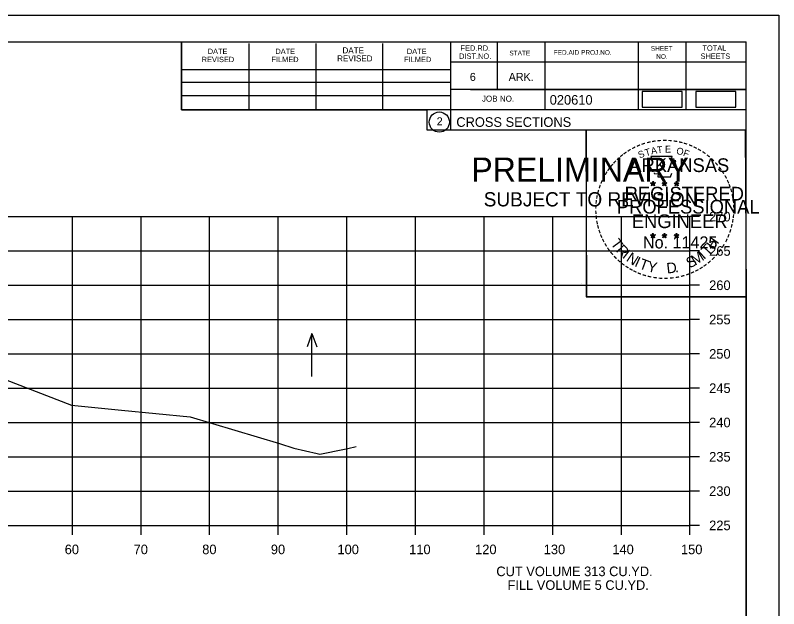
# Model space of a CAD drawing. Extents: x 1103485 to 1107180, y 2010593 to 2011873.
# Drawn here: x 1107068.9 to 1107180.1, y 2011573 to 2011659.5 of the extents above; entities that cross this region are included whole.
import ezdxf

# ---------------------------------------------------------------- set-up
doc = ezdxf.new("R2010")
doc.units = 0
for name, color, linetype in [('R_Axis', 7, 'Continuous'), ('R_Axis Annot', 7, 'Continuous'), ('R_Border', 7, 'Continuous'), ('R_Border PE', 7, 'Continuous'), ('R_Border Prem', 7, 'Continuous'), ('R_Exist Surface', 7, 'Continuous'), ('R_Grid', 7, 'Continuous'), ('R_No Plot', 7, 'Continuous'), ('R_Water', 7, 'Continuous'), ('R_Water Annot', 7, 'Continuous')]:
    doc.layers.add(name, color=color, linetype=linetype)

msp = doc.modelspace()

# ---------------------------------------------------------------- linework, layer by layer
at = {"layer": 'R_Axis'}
for p, q in [((1107167.18, 2011585.17), (1107167.18, 2011630.17)), ((1107168.58, 2011630.17), (1107167.18, 2011630.17)), ((1107168.58, 2011625.17), (1107167.18, 2011625.17)), ((1107168.58, 2011620.17), (1107167.18, 2011620.17)), ((1107168.58, 2011615.17), (1107167.18, 2011615.17)), ((1107168.58, 2011610.17), (1107167.18, 2011610.17)), ((1107168.58, 2011605.17), (1107167.18, 2011605.17)), ((1107168.58, 2011600.17), (1107167.18, 2011600.17)), ((1107168.58, 2011595.17), (1107167.18, 2011595.17)), ((1107168.58, 2011590.17), (1107167.18, 2011590.17)), ((1106867.18, 2011585.17), (1107167.18, 2011585.17)), ((1107077.18, 2011583.77), (1107077.18, 2011585.17)), ((1107087.18, 2011583.77), (1107087.18, 2011585.17)), ((1107097.18, 2011583.77), (1107097.18, 2011585.17)), ((1107107.18, 2011583.77), (1107107.18, 2011585.17)), ((1107117.18, 2011583.77), (1107117.18, 2011585.17)), ((1107127.18, 2011583.77), (1107127.18, 2011585.17)), ((1107137.18, 2011583.77), (1107137.18, 2011585.17)), ((1107147.18, 2011583.77), (1107147.18, 2011585.17)), ((1107157.18, 2011583.77), (1107157.18, 2011585.17)), ((1107167.18, 2011583.77), (1107167.18, 2011585.17)), ((1107168.58, 2011585.17), (1107167.18, 2011585.17))]:
    msp.add_line(p, q, dxfattribs=at)
at = {"layer": 'R_Border'}
for p, q in [((1106859.18, 2011655.63), (1107175.36, 2011655.63)), ((1107093.1, 2011645.75), (1107093.1, 2011655.63)), ((1107102.96, 2011645.75), (1107102.96, 2011655.43)), ((1107112.72, 2011645.75), (1107112.72, 2011655.43)), ((1107122.4, 2011645.75), (1107122.4, 2011655.43)), ((1107132.26, 2011655.63), (1107132.26, 2011642.83)), ((1107139.1, 2011655.63), (1107139.1, 2011648.69)), ((1107146.04, 2011655.63), (1107146.04, 2011645.75)), ((1107159.62, 2011655.63), (1107159.62, 2011645.75)), ((1107166.56, 2011655.63), (1107166.56, 2011645.75)), ((1107175.36, 2011450.17), (1107175.36, 2011655.63)), ((1107175.36, 2011652.69), (1107132.26, 2011652.69)), ((1107175.36, 2011652.71), (1107175.36, 2011652.71)), ((1107093.1, 2011651.61), (1107132.26, 2011651.61)), ((1107093.1, 2011649.75), (1107132.26, 2011649.75)), ((1107175.36, 2011648.69), (1107132.26, 2011648.69)), ((1107135.22, 2011648.69), (1107175.36, 2011648.69)), ((1107093.1, 2011645.75), (1107093.1, 2011647.81)), ((1107093.1, 2011647.81), (1107132.26, 2011647.81)), ((1107175.36, 2011645.75), (1107093.1, 2011645.75)), ((1107132.26, 2011642.83), (1107175.36, 2011642.83))]:
    msp.add_line(p, q, dxfattribs=at)
msp.add_circle((1107130.65, 2011643.96), 1.47, dxfattribs=at)
at = {"layer": 'R_Border PE'}
for p, q in [((1107161.45, 2011635.08), (1107161.8, 2011634.97)), ((1107161.45, 2011635.08), (1107161.7, 2011635.04)), ((1107161.45, 2011635.08), (1107161.69, 2011634.96)), ((1107161.8, 2011635.34), (1107161.76, 2011635.09)), ((1107161.8, 2011634.97), (1107161.8, 2011635.34)), ((1107161.8, 2011635.34), (1107161.85, 2011635.09)), ((1107162.14, 2011635.08), (1107161.8, 2011634.97)), ((1107162.14, 2011635.08), (1107161.86, 2011635.03)), ((1107162.14, 2011635.08), (1107161.94, 2011634.98)), ((1107163.12, 2011635.08), (1107163.47, 2011634.97)), ((1107163.12, 2011635.08), (1107163.37, 2011635.04)), ((1107163.12, 2011635.08), (1107163.36, 2011634.96)), ((1107163.47, 2011635.34), (1107163.43, 2011635.09)), ((1107163.47, 2011634.97), (1107163.47, 2011635.34)), ((1107163.47, 2011635.34), (1107163.52, 2011635.09)), ((1107163.81, 2011635.08), (1107163.47, 2011634.97)), ((1107163.81, 2011635.08), (1107163.53, 2011635.03)), ((1107163.81, 2011635.08), (1107163.61, 2011634.98)), ((1107164.88, 2011635.07), (1107165.23, 2011634.96)), ((1107164.88, 2011635.07), (1107165.14, 2011635.03)), ((1107164.88, 2011635.07), (1107165.12, 2011634.95)), ((1107165.23, 2011635.33), (1107165.19, 2011635.07)), ((1107165.23, 2011634.96), (1107165.23, 2011635.33)), ((1107165.23, 2011635.33), (1107165.28, 2011635.08)), ((1107165.58, 2011635.07), (1107165.23, 2011634.96)), ((1107165.58, 2011635.07), (1107165.29, 2011635.02)), ((1107165.58, 2011635.07), (1107165.37, 2011634.97)), ((1107161.58, 2011634.68), (1107161.8, 2011634.97)), ((1107161.58, 2011634.68), (1107161.71, 2011634.92)), ((1107161.58, 2011634.68), (1107161.8, 2011634.89)), ((1107162.01, 2011634.68), (1107161.8, 2011634.97)), ((1107162.01, 2011634.68), (1107161.8, 2011634.89)), ((1107162.01, 2011634.68), (1107161.87, 2011634.97)), ((1107163.25, 2011634.68), (1107163.47, 2011634.97)), ((1107163.25, 2011634.68), (1107163.38, 2011634.92)), ((1107163.25, 2011634.68), (1107163.47, 2011634.89)), ((1107163.68, 2011634.68), (1107163.47, 2011634.97)), ((1107163.68, 2011634.68), (1107163.47, 2011634.89)), ((1107163.68, 2011634.68), (1107163.54, 2011634.97)), ((1107165.02, 2011634.66), (1107165.23, 2011634.96)), ((1107165.02, 2011634.66), (1107165.14, 2011634.91)), ((1107165.02, 2011634.66), (1107165.23, 2011634.88)), ((1107165.44, 2011634.66), (1107165.23, 2011634.96)), ((1107165.44, 2011634.66), (1107165.23, 2011634.88)), ((1107165.44, 2011634.66), (1107165.31, 2011634.95)), ((1107161.44, 2011627.51), (1107161.79, 2011627.4)), ((1107161.44, 2011627.51), (1107161.7, 2011627.47)), ((1107161.44, 2011627.51), (1107161.68, 2011627.39)), ((1107161.58, 2011627.1), (1107161.79, 2011627.4)), ((1107161.58, 2011627.1), (1107161.7, 2011627.35)), ((1107161.58, 2011627.1), (1107161.79, 2011627.32)), ((1107161.79, 2011627.76), (1107161.75, 2011627.51)), ((1107161.79, 2011627.4), (1107161.79, 2011627.76)), ((1107161.79, 2011627.76), (1107161.84, 2011627.51)), ((1107162.14, 2011627.51), (1107161.79, 2011627.4)), ((1107162.01, 2011627.1), (1107161.79, 2011627.4)), ((1107162.01, 2011627.1), (1107161.79, 2011627.32)), ((1107162.14, 2011627.51), (1107161.85, 2011627.46)), ((1107162.01, 2011627.1), (1107161.87, 2011627.39)), ((1107162.14, 2011627.51), (1107161.94, 2011627.41)), ((1107163.11, 2011627.51), (1107163.46, 2011627.4)), ((1107163.11, 2011627.51), (1107163.37, 2011627.47)), ((1107163.11, 2011627.51), (1107163.35, 2011627.39)), ((1107163.25, 2011627.1), (1107163.46, 2011627.4)), ((1107163.25, 2011627.1), (1107163.37, 2011627.35)), ((1107163.25, 2011627.1), (1107163.46, 2011627.32)), ((1107163.46, 2011627.76), (1107163.42, 2011627.51)), ((1107163.46, 2011627.4), (1107163.46, 2011627.76)), ((1107163.46, 2011627.76), (1107163.51, 2011627.51)), ((1107163.81, 2011627.51), (1107163.46, 2011627.4)), ((1107163.68, 2011627.1), (1107163.46, 2011627.4)), ((1107163.68, 2011627.1), (1107163.46, 2011627.32)), ((1107163.81, 2011627.51), (1107163.52, 2011627.46)), ((1107163.68, 2011627.1), (1107163.54, 2011627.39)), ((1107163.81, 2011627.51), (1107163.61, 2011627.41)), ((1107164.88, 2011627.5), (1107165.23, 2011627.39)), ((1107164.88, 2011627.5), (1107165.13, 2011627.46)), ((1107164.88, 2011627.5), (1107165.12, 2011627.38)), ((1107165.01, 2011627.09), (1107165.23, 2011627.39)), ((1107165.01, 2011627.09), (1107165.14, 2011627.34)), ((1107165.01, 2011627.09), (1107165.23, 2011627.31)), ((1107165.23, 2011627.75), (1107165.19, 2011627.5)), ((1107165.23, 2011627.39), (1107165.23, 2011627.75)), ((1107165.23, 2011627.75), (1107165.28, 2011627.5)), ((1107165.58, 2011627.5), (1107165.23, 2011627.39)), ((1107165.44, 2011627.09), (1107165.23, 2011627.39)), ((1107165.44, 2011627.09), (1107165.23, 2011627.31)), ((1107165.58, 2011627.5), (1107165.29, 2011627.45)), ((1107165.44, 2011627.09), (1107165.31, 2011627.38)), ((1107165.58, 2011627.5), (1107165.37, 2011627.4))]:
    msp.add_line(p, q, dxfattribs=at)
for points in [[(1107161.49, 2011638.96), (1107161.76, 2011638.13)], [(1107165, 2011638.04), (1107165.14, 2011638.32), (1107164.46, 2011638.3), (1107164.61, 2011638.96), (1107161.49, 2011638.96)], [(1107161.98, 2011636.54), (1107161.98, 2011636.45), (1107162.54, 2011636.43), (1107162.49, 2011635.96), (1107164.36, 2011635.96), (1107164.56, 2011636.5)], [(1107161.8, 2011635.34), (1107162.01, 2011634.68), (1107161.45, 2011635.08), (1107162.14, 2011635.08), (1107161.58, 2011634.68), (1107161.8, 2011635.34)], [(1107163.47, 2011635.34), (1107163.68, 2011634.68), (1107163.12, 2011635.08), (1107163.81, 2011635.08), (1107163.25, 2011634.68), (1107163.47, 2011635.34)], [(1107165.23, 2011635.33), (1107165.44, 2011634.66), (1107164.88, 2011635.07), (1107165.58, 2011635.07), (1107165.02, 2011634.66), (1107165.23, 2011635.33)], [(1107161.79, 2011627.76), (1107162.01, 2011627.1), (1107161.44, 2011627.51), (1107162.14, 2011627.51), (1107161.58, 2011627.1), (1107161.79, 2011627.76)], [(1107163.46, 2011627.76), (1107163.68, 2011627.1), (1107163.11, 2011627.51), (1107163.81, 2011627.51), (1107163.25, 2011627.1), (1107163.46, 2011627.76)], [(1107165.23, 2011627.75), (1107165.44, 2011627.09), (1107164.88, 2011627.5), (1107165.58, 2011627.5), (1107165.01, 2011627.09), (1107165.23, 2011627.75)]]:
    msp.add_lwpolyline(points, dxfattribs=at)
for centre, radius in [((1107161.8, 2011634.97), 0.172), ((1107161.8, 2011634.97), 0.145), ((1107161.8, 2011634.97), 0.116), ((1107161.8, 2011634.97), 0.0991), ((1107161.8, 2011634.97), 0.0747), ((1107163.47, 2011634.97), 0.172), ((1107163.47, 2011634.97), 0.145), ((1107163.47, 2011634.97), 0.116), ((1107163.47, 2011634.97), 0.0991), ((1107163.47, 2011634.97), 0.0747), ((1107165.23, 2011634.96), 0.172), ((1107165.23, 2011634.96), 0.145), ((1107165.23, 2011634.96), 0.116), ((1107165.23, 2011634.96), 0.0991), ((1107161.8, 2011634.97), 0.0495), ((1107161.8, 2011634.97), 0.0296), ((1107163.47, 2011634.97), 0.0495), ((1107163.47, 2011634.97), 0.0296), ((1107165.23, 2011634.96), 0.0747), ((1107165.23, 2011634.96), 0.0495), ((1107165.23, 2011634.96), 0.0296), ((1107161.79, 2011627.4), 0.172), ((1107161.79, 2011627.4), 0.145), ((1107161.79, 2011627.4), 0.116), ((1107161.79, 2011627.4), 0.0991), ((1107161.79, 2011627.4), 0.0747), ((1107161.79, 2011627.4), 0.0495), ((1107161.79, 2011627.4), 0.0296), ((1107163.46, 2011627.4), 0.172), ((1107163.46, 2011627.4), 0.145), ((1107163.46, 2011627.4), 0.116), ((1107163.46, 2011627.4), 0.0991), ((1107163.46, 2011627.4), 0.0747), ((1107163.46, 2011627.4), 0.0495), ((1107163.46, 2011627.4), 0.0296), ((1107165.23, 2011627.39), 0.172), ((1107165.23, 2011627.39), 0.145), ((1107165.23, 2011627.39), 0.116), ((1107165.23, 2011627.39), 0.0991), ((1107165.23, 2011627.39), 0.0747), ((1107165.23, 2011627.39), 0.0495), ((1107165.23, 2011627.39), 0.0296)]:
    msp.add_circle(centre, radius, dxfattribs=at)
at = {"layer": 'R_Exist Surface'}
msp.add_lwpolyline([(1107058.31, 2011609.94), (1107077.03, 2011602.69), (1107084.35, 2011601.97), (1107094.32, 2011601), (1107107.35, 2011597.1), (1107109.47, 2011596.44), (1107112.84, 2011595.63), (1107113.26, 2011595.53), (1107116.85, 2011596.28), (1107117.3, 2011596.38), (1107118.54, 2011596.65)], dxfattribs=at)
at = {"layer": 'R_Grid'}
for p, q in [((1106867.18, 2011630.17), (1107167.18, 2011630.17)), ((1107077.18, 2011585.17), (1107077.18, 2011630.17)), ((1107087.18, 2011585.17), (1107087.18, 2011630.17)), ((1107097.18, 2011585.17), (1107097.18, 2011630.17)), ((1107107.18, 2011585.17), (1107107.18, 2011630.17)), ((1107117.18, 2011585.17), (1107117.18, 2011630.17)), ((1107127.18, 2011585.17), (1107127.18, 2011630.17)), ((1107137.18, 2011585.17), (1107137.18, 2011630.17)), ((1107147.18, 2011585.17), (1107147.18, 2011630.17)), ((1107157.18, 2011585.17), (1107157.18, 2011630.17)), ((1107167.18, 2011585.17), (1107167.18, 2011630.17)), ((1106867.18, 2011625.17), (1107167.18, 2011625.17)), ((1106867.18, 2011620.17), (1107167.18, 2011620.17)), ((1106867.18, 2011615.17), (1107167.18, 2011615.17)), ((1106867.18, 2011610.17), (1107167.18, 2011610.17)), ((1106867.18, 2011605.17), (1107167.18, 2011605.17)), ((1106867.18, 2011600.17), (1107167.18, 2011600.17)), ((1106867.18, 2011595.17), (1107167.18, 2011595.17)), ((1106867.18, 2011590.17), (1107167.18, 2011590.17)), ((1106867.18, 2011585.17), (1107167.18, 2011585.17))]:
    msp.add_line(p, q, dxfattribs=at)
at = {"layer": 'R_No Plot'}
for p, q in [((1106846.78, 2011659.52), (1107180.12, 2011659.52)), ((1107151.4, 2011620.37), (1107151.4, 2011620.37))]:
    msp.add_line(p, q, dxfattribs=at)
for points in [[(1106846.78, 2011659.52), (1107180.12, 2011659.52), (1107180.12, 2011446.19), (1106846.78, 2011446.19)], [(1107093.1, 2011655.63), (1107093.1, 2011645.75), (1107128.84, 2011645.75), (1107128.84, 2011642.83), (1107152.04, 2011642.83), (1107152.04, 2011618.5), (1107175.36, 2011618.5), (1107175.36, 2011450.17), (1106859.18, 2011450.17), (1106859.18, 2011655.63)], [(1107152.04, 2011642.83), (1107175.24, 2011642.83), (1107175.36, 2011618.5), (1107152.16, 2011618.5)]]:
    msp.add_lwpolyline(points, close=True, dxfattribs=at)
at = {"layer": 'R_Water'}
for points in [[(1107160.2, 2011646.12), (1107166.03, 2011646.12), (1107166.03, 2011648.43), (1107160.2, 2011648.43)], [(1107168.04, 2011646.12), (1107173.87, 2011646.12), (1107173.87, 2011648.43), (1107168.04, 2011648.43)]]:
    msp.add_lwpolyline(points, close=True, dxfattribs=at)
at = {"layer": 'R_Water Annot'}
for p, q in [((1107112.08, 2011613.14), (1107111.38, 2011611.22)), ((1107112.08, 2011606.86), (1107112.08, 2011613.14)), ((1107112.08, 2011613.14), (1107112.78, 2011611.22))]:
    msp.add_line(p, q, dxfattribs=at)

# ---------------------------------------------------------------- texts
at = {"layer": 'R_Axis Annot'}
for s, p in [('270', (1107169.98, 2011629.47)), ('265', (1107169.98, 2011624.47)), ('260', (1107169.98, 2011619.47)), ('255', (1107169.98, 2011614.47)), ('250', (1107169.98, 2011609.47)), ('245', (1107169.98, 2011604.47)), ('240', (1107169.98, 2011599.47)), ('235', (1107169.98, 2011594.47)), ('230', (1107169.98, 2011589.47)), ('225', (1107169.98, 2011584.47)), ('60', (1107076.06, 2011580.97)), ('70', (1107086.1, 2011580.97)), ('80', (1107096.1, 2011580.97)), ('90', (1107106.1, 2011580.97)), ('100', (1107115.81, 2011580.97)), ('110', (1107126.26, 2011580.97)), ('120', (1107135.87, 2011580.97)), ('130', (1107145.87, 2011580.97)), ('140', (1107155.87, 2011580.97)), ('150', (1107165.87, 2011580.97)), ('CUT VOLUME 313 CU.YD.', (1107138.96, 2011577.77)), ('FILL VOLUME 5 CU.YD.', (1107140.59, 2011575.77))]:
    msp.add_text(s, height=1.4, dxfattribs=at).set_placement(p)
at = {"layer": 'R_Border'}
for s, height, p in [('FED.RD.', 0.782, (1107133.74, 2011654.35)), ('TOTAL', 0.782, (1107169, 2011654.35)), ('DATE', 0.782, (1107096.9, 2011653.87)), ('DATE', 0.782, (1107106.76, 2011653.87)), ('DATE', 0.879, (1107116.54, 2011653.97)), ('DATE', 0.782, (1107125.92, 2011653.87)), ('DIST.NO.', 0.782, (1107133.54, 2011653.17)), ('STATE', 0.684, (1107140.86, 2011653.67)), ('FED.AID PROJ.NO.', 0.684, (1107147.32, 2011653.77)), ('SHEET', 0.684, (1107161.48, 2011654.35)), ('SHEETS', 0.782, (1107168.72, 2011653.17)), ('REVISED', 0.782, (1107096.02, 2011652.69)), ('FILMED', 0.782, (1107106.18, 2011652.69)), ('REVISED', 0.879, (1107115.76, 2011652.79)), ('FILMED', 0.782, (1107125.52, 2011652.69)), ('NO.', 0.684, (1107162.26, 2011653.17)), ('6', 1.17, (1107135.1, 2011649.95)), ('ARK.', 1.172, (1107140.76, 2011649.95)), ('JOB NO.', 0.879, (1107136.86, 2011646.93)), ('020610', 1.4, (1107146.74, 2011646.49)), ('2', 1.17, (1107130.27, 2011643.48)), ('CROSS SECTIONS', 1.4, (1107133.13, 2011643.26))]:
    msp.add_text(s, height=height, rotation=360, dxfattribs=at).set_placement(p)
at = {"layer": 'R_Border PE'}
for s, height, rotation, p in [('-', 1.6, 24.3072, (1107159.6, 2011639.82)), ('-', 1.6, 19.1761, (1107160.24, 2011640.09)), ('-', 1.6, 13.6301, (1107160.99, 2011640.33)), ('-', 1.6, 10.2193, (1107161.67, 2011640.49)), ('-', 1.6, 5.8968, (1107162.39, 2011640.6)), ('-', 1.6, 0.1862, (1107163.17, 2011640.67)), ('-', 1.6, 357.743, (1107163.89, 2011640.66)), ('-', 1.6, 352.1617, (1107164.63, 2011640.6)), ('-', 1.6, 347.2049, (1107165.35, 2011640.49)), ('-', 1.6, 342.3362, (1107165.99, 2011640.34)), ('-', 1.6, 337.8551, (1107166.72, 2011640.11)), ('-', 1.6, 36.2317, (1107157.8, 2011638.74)), ('-', 1.6, 34.0636, (1107158.37, 2011639.13)), ('-', 1.6, 28.7918, (1107158.97, 2011639.5)), ('S', 1, 21.594, (1107159.84, 2011638.64)), ('T', 1, 16.4036, (1107160.76, 2011638.97)), ('A', 1, 11.2132, (1107161.58, 2011639.22)), ('T', 1, 6.0228, (1107162.43, 2011639.39)), ('E', 1, 0.8323, (1107163.54, 2011639.5)), ('O', 1, 350.4515, (1107165.14, 2011639.29)), ('F', 1, 340.0707, (1107166.1, 2011639.06)), ('-', 1.6, 334.1211, (1107167.35, 2011639.84)), ('-', 1.6, 329.6409, (1107167.93, 2011639.56)), ('-', 1.6, 325.8627, (1107168.58, 2011639.2)), ('-', 1.6, 48.423, (1107156.44, 2011637.46)), ('-', 1.6, 42.9622, (1107156.89, 2011637.94)), ('-', 1.6, 38.9507, (1107157.32, 2011638.36)), ('ARKANSAS', 2, 360, (1107158.34, 2011636.67)), ('-', 1.6, 320.5297, (1107169.19, 2011638.77)), ('-', 1.6, 315.5786, (1107169.78, 2011638.28)), ('-', 1.6, 54.2325, (1107155.62, 2011636.41)), ('-', 1.6, 50.6142, (1107156.04, 2011636.98)), ('-', 1.6, 309.8797, (1107170.35, 2011637.73)), ('-', 1.6, 306.6522, (1107170.88, 2011637.13)), ('-', 1.6, 58.0706, (1107155.3, 2011635.88)), ('-', 1.4, 303.6753, (1107171.36, 2011636.56)), ('-', 1.6, 299.6684, (1107171.68, 2011635.96)), ('-', 1.6, 67.7743, (1107154.73, 2011634.66)), ('-', 1.6, 62.8713, (1107154.98, 2011635.27)), ('-', 1.6, 294.6628, (1107172.01, 2011635.34)), ('-', 1.6, 75.461, (1107154.31, 2011633.32)), ('-', 1.6, 72.3945, (1107154.51, 2011634.03)), ('REGISTERED', 2, 360, (1107157.66, 2011632.52)), ('DWB', 0.01, 360, (1107161.78, 2011634.97)), ('DWB', 0.01, 360, (1107163.45, 2011634.97)), ('DWB', 0.01, 360, (1107165.22, 2011634.96)), ('-', 1.6, 290.5728, (1107172.26, 2011634.77)), ('-', 1.6, 285.1233, (1107172.5, 2011634.19)), ('-', 1.6, 81.2013, (1107154.18, 2011632.6)), ('-', 1.6, 280.5493, (1107172.7, 2011633.45)), ('-', 1.6, 89.0622, (1107154.08, 2011631.21)), ('-', 1.6, 85.1863, (1107154.1, 2011631.91)), ('PROFESSIONAL', 2, 360, (1107156.52, 2011630.62)), ('-', 1.6, 276.5962, (1107172.86, 2011632.68)), ('-', 1.6, 274.3301, (1107172.92, 2011631.96)), ('-', 1.6, 94.1959, (1107154.11, 2011630.49)), ('-', 1.6, 269.9407, (1107172.95, 2011631.32)), ('-', 1.6, 98.9479, (1107154.18, 2011629.82)), ('-', 1.6, 101.7149, (1107154.32, 2011629.09)), ('ENGINEER', 2, 360, (1107158.7, 2011628.5)), ('-', 1.6, 260.9953, (1107172.86, 2011630)), ('-', 1.6, 263.5172, (1107172.94, 2011630.66)), ('-', 1.6, 105.4578, (1107154.48, 2011628.49)), ('-', 1.6, 255.7626, (1107172.75, 2011629.33)), ('-', 1.6, 109.0874, (1107154.7, 2011627.86)), ('-', 1.6, 114.0643, (1107154.95, 2011627.26)), ('No. 11425', 1.757, 360, (1107160.33, 2011625.54)), ('DWB', 0.01, 360, (1107161.78, 2011627.39)), ('DWB', 0.01, 360, (1107163.45, 2011627.4)), ('DWB', 0.01, 360, (1107165.22, 2011627.39)), ('-', 1.6, 247.8887, (1107172.35, 2011627.93)), ('-', 1.6, 252.8681, (1107172.57, 2011628.61)), ('-', 1.6, 115.7289, (1107155.25, 2011626.65)), ('-', 1.6, 120.4471, (1107155.61, 2011626.06)), ('T', 1.54, 306.0406, (1107155.55, 2011626.24)), ('T', 1.54, 46.6444, (1107169.78, 2011624.33)), ('H', 1.54, 54.6088, (1107170.67, 2011625.27)), ('-', 1.6, 239.0712, (1107171.69, 2011626.55)), ('-', 1.6, 244.6197, (1107172.09, 2011627.3)), ('-', 1.6, 125.8934, (1107156.01, 2011625.5)), ('-', 1.6, 130.7181, (1107156.48, 2011624.95)), ('R', 1.54, 314.005, (1107156.32, 2011625.19)), ('I', 1.54, 321.9694, (1107157.22, 2011624.26)), ('M', 1.54, 32.6563, (1107167.94, 2011623.01)), ('I', 1.54, 42.1136, (1107169.22, 2011623.85)), ('-', 1.6, 233.8452, (1107171.29, 2011625.9)), ('-', 1.6, 134.2238, (1107156.99, 2011624.4)), ('-', 1.6, 138.9338, (1107157.52, 2011623.94)), ('N', 1.54, 326.5002, (1107157.78, 2011623.79)), ('I', 1.54, 335.3603, (1107158.99, 2011623)), ('T', 1.54, 339.8912, (1107159.65, 2011622.67)), ('S', 1.54, 26.9312, (1107167.1, 2011622.6)), ('-', 1.6, 225.7653, (1107170.38, 2011624.77)), ('-', 1.6, 231.2538, (1107170.86, 2011625.33)), ('-', 1.6, 144.6463, (1107158.07, 2011623.53)), ('-', 1.6, 148.0898, (1107158.64, 2011623.16)), ('Y', 1.54, 347.8556, (1107160.87, 2011622.23)), ('D', 1.54, 6.3969, (1107163.85, 2011621.87)), ('-', 1.6, 212.2491, (1107168.78, 2011623.4)), ('-', 1.6, 215.7363, (1107169.31, 2011623.79)), ('-', 1.6, 221.0851, (1107169.86, 2011624.26)), ('-', 1.6, 151.5704, (1107159.21, 2011622.84)), ('-', 1.6, 154.6002, (1107159.74, 2011622.59)), ('-', 1.6, 158.5612, (1107160.36, 2011622.33)), ('-', 1.6, 162.7983, (1107161.05, 2011622.12)), ('.', 1.54, 13.7642, (1107165.05, 2011622)), ('-', 1.6, 200.7184, (1107166.98, 2011622.46)), ('-', 1.6, 204.2516, (1107167.6, 2011622.74)), ('-', 1.6, 207.3568, (1107168.22, 2011623.05)), ('-', 1.6, 167.5555, (1107161.76, 2011621.96)), ('-', 1.6, 173.1155, (1107162.53, 2011621.85)), ('-', 1.6, 176.5183, (1107163.28, 2011621.79)), ('-', 1.6, 181.5918, (1107164.03, 2011621.81)), ('-', 1.6, 185.8167, (1107164.84, 2011621.89)), ('-', 1.6, 191.2858, (1107165.57, 2011622.02)), ('-', 1.6, 195.4743, (1107166.3, 2011622.22))]:
    msp.add_text(s, height=height, rotation=rotation, dxfattribs=at).set_placement(p)
at = {"layer": 'R_Border Prem'}
for s, height, p in [('PRELIMINARY', 3.5, (1107135.31, 2011635.29)), ('DWB', 0.01, (1107136.06, 2011637.14)), ('SUBJECT TO REVISION', 2.0751, (1107137.12, 2011631.66))]:
    msp.add_text(s, height=height, rotation=360, dxfattribs=at).set_placement(p)

doc.saveas('drawing.dxf')
